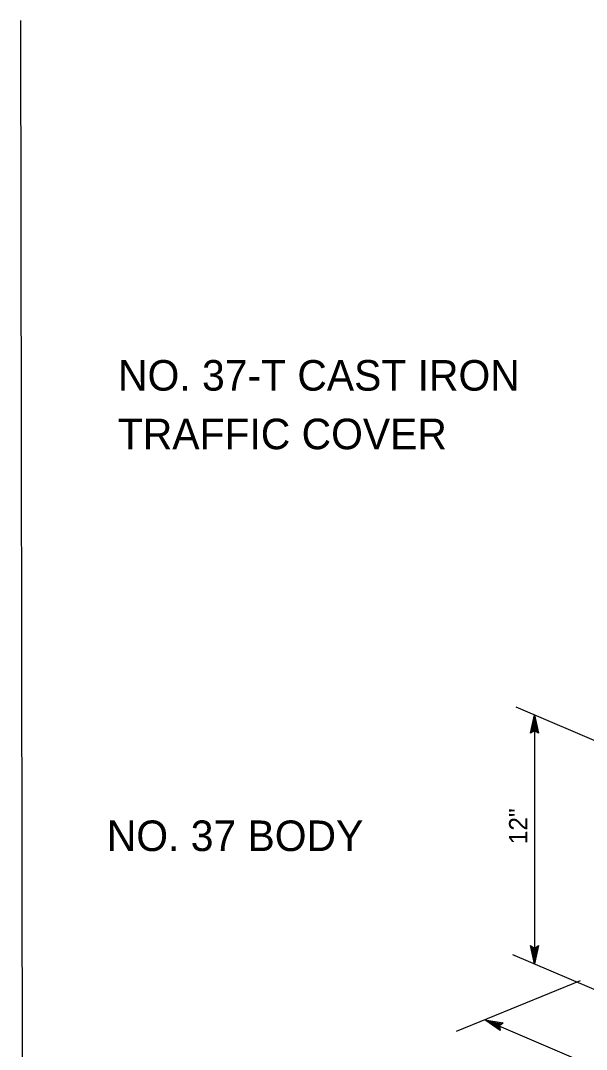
# Model space of a CAD drawing. Extents: x -121933 to -117742, y -103160 to -100084.
# Drawn here: x -121211 to -121025.8, y -101489.7 to -101153.1 of the extents above; entities that cross this region are included whole.
import ezdxf

# ---------------------------------------------------------------- set-up
doc = ezdxf.new("R2010")
doc.units = 0
for name, color, linetype in [('G-MARK', 7, 'Continuous'), ('G-TEXT', 7, 'Continuous'), ('Misc CnstDet(22)', 7, 'Continuous')]:
    doc.layers.add(name, color=color, linetype=linetype)

msp = doc.modelspace()

# ---------------------------------------------------------------- linework, layer by layer
at = {"layer": 'G-MARK'}
for p, q in [((-121015.99, -101391.76), (-121048.75, -101377.76)), ((-121042.76, -101380.32), (-121042.76, -101461.79)), ((-121014.23, -101473.99), (-121049.85, -101458.76)), ((-121027.87, -101467.3), (-121068.39, -101483.86)), ((-121059.07, -101480.05), (-120953.15, -101525.32))]:
    msp.add_line(p, q, dxfattribs=at)
at = {"layer": 'G-TEXT'}
for p, q in [((-121044.1, -101386.32), (-121042.76, -101380.32)), ((-121042.76, -101380.32), (-121042.76, -101380.32)), ((-121042.76, -101380.32), (-121041.43, -101386.32)), ((-121043.75, -101386.1), (-121042.76, -101381.7)), ((-121043.39, -101385.87), (-121042.77, -101383.08)), ((-121043.04, -101385.69), (-121042.77, -101384.46)), ((-121042.77, -101383.08), (-121042.14, -101385.9)), ((-121042.77, -101384.46), (-121042.5, -101385.67)), ((-121042.76, -101381.71), (-121041.79, -101386.08)), ((-121042.76, -101385.52), (-121044.1, -101386.32)), ((-121044.1, -101386.32), (-121044.1, -101386.32)), ((-121041.43, -101386.32), (-121042.76, -101385.52)), ((-121041.43, -101386.32), (-121041.43, -101386.32)), ((-121042.76, -101461.79), (-121044.09, -101455.79)), ((-121044.09, -101455.79), (-121044.09, -101455.79)), ((-121044.09, -101455.79), (-121042.76, -101456.59)), ((-121042.77, -101460.4), (-121043.73, -101456.03)), ((-121042.76, -101459.03), (-121043.39, -101456.2)), ((-121042.76, -101457.65), (-121043.03, -101456.44)), ((-121042.76, -101456.59), (-121041.42, -101455.79)), ((-121041.42, -101455.79), (-121042.76, -101461.79)), ((-121041.78, -101456.01), (-121042.76, -101460.41)), ((-121042.14, -101456.24), (-121042.76, -101459.03)), ((-121042.49, -101456.42), (-121042.76, -101457.65)), ((-121041.42, -101455.79), (-121041.42, -101455.79)), ((-121042.76, -101461.79), (-121042.76, -101461.79)), ((-121054.03, -101483.57), (-121059.07, -101480.05)), ((-121059.07, -101480.05), (-121059.07, -101480.05)), ((-121059.07, -101480.05), (-121053.01, -101481.1)), ((-121054.09, -101483.16), (-121057.79, -101480.58)), ((-121057.78, -101480.58), (-121053.37, -101481.35)), ((-121054.17, -101482.74), (-121056.51, -101481.1)), ((-121056.51, -101481.1), (-121053.66, -101481.6)), ((-121054.2, -101482.35), (-121055.24, -101481.63)), ((-121055.24, -101481.63), (-121054.02, -101481.84)), ((-121053.01, -101481.1), (-121054.26, -101482.03)), ((-121054.26, -101482.03), (-121054.03, -101483.57)), ((-121053.01, -101481.1), (-121053.01, -101481.1)), ((-121054.03, -101483.57), (-121054.03, -101483.57))]:
    msp.add_line(p, q, dxfattribs=at)
at = {"layer": 'Misc CnstDet(22)'}
msp.add_line((-121211.03, -101153.11), (-121209.67, -102136.14), dxfattribs=at)

# ---------------------------------------------------------------- texts
for s, p in [('NO. 37-T CAST IRON', (-121179.11, -101274.19)), ('TRAFFIC COVER', (-121179.18, -101293.36)), ('NO. 37 BODY', (-121182.8, -101424.84))]:
    msp.add_text(s, height=10, dxfattribs=at).set_placement(p)
msp.add_text('12"', height=6, rotation=90.168, dxfattribs=at).set_placement((-121045.09, -101422.62))

doc.saveas('drawing.dxf')
